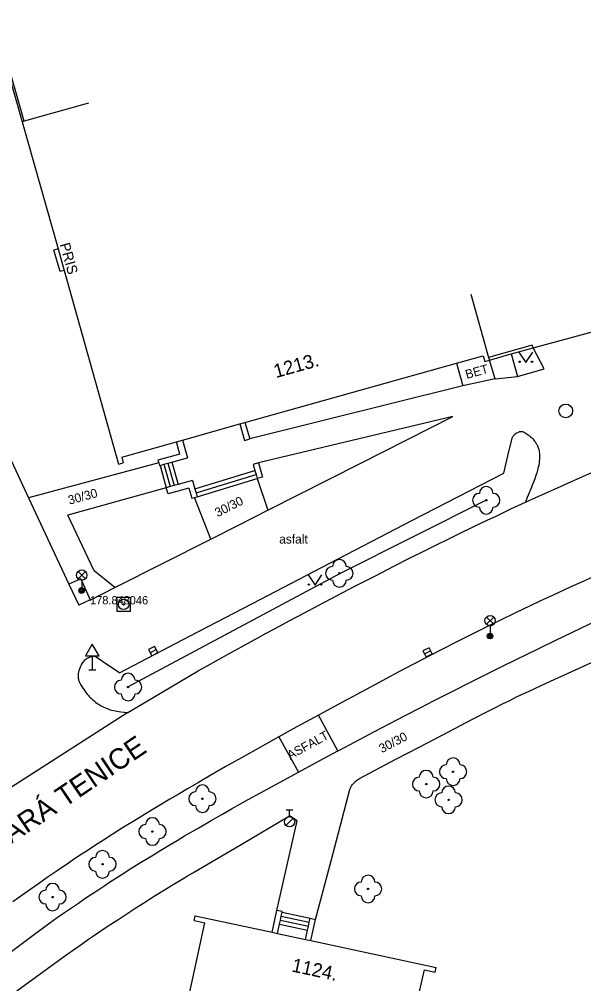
# Model space of a CAD drawing. Extents: x -538441 to -536770, y -1181008 to -1179809.
# Drawn here: x -538238.9 to -538197.8, y -1180684 to -1180613.8 of the extents above; entities that cross this region are included whole.
import ezdxf

# ---------------------------------------------------------------- set-up
doc = ezdxf.new("R2010")
doc.units = 0
for name, color, linetype in [('Vrstva 10', 7, 'Continuous'), ('Vrstva 11', 7, 'Continuous'), ('Vrstva 21', 7, 'Continuous'), ('Vrstva 22', 7, 'Continuous'), ('Vrstva 23', 7, 'Continuous'), ('Vrstva 24', 7, 'Continuous'), ('Vrstva 26', 7, 'Continuous'), ('Vrstva 27', 7, 'Continuous'), ('Vrstva 28', 7, 'Continuous'), ('Vrstva 33', 7, 'Continuous'), ('Vrstva 34', 7, 'Continuous'), ('Vrstva 36', 7, 'Continuous'), ('Vrstva 40', 7, 'Continuous'), ('Vrstva 41', 7, 'Continuous'), ('Vrstva 47', 7, 'Continuous'), ('Vrstva 49', 7, 'Continuous'), ('Vrstva 5', 7, 'Continuous'), ('Vrstva 7', 7, 'Continuous'), ('Vrstva 8', 7, 'Continuous')]:
    doc.layers.add(name, color=color, linetype=linetype)

msp = doc.modelspace()

# ---------------------------------------------------------------- linework, layer by layer
at = {"layer": 'Vrstva 10'}
for p, q in [((-538199.896, -1180648.017), (-538198.65, -1180647.463)), ((-538209.361, -1180652.506), (-538208.449, -1180652.053)), ((-538219.161, -1180657.587), (-538218.102, -1180657.023)), ((-538202.747, -1180657.031), (-538203.82, -1180657.55)), ((-538230.97, -1180664.27), (-538240.97, -1180670.69)), ((-538219.959, -1180666.056), (-538221.314, -1180666.809))]:
    msp.add_line(p, q, dxfattribs=at)
for points in [[(-538198.65, -1180647.463), (-538197.557, -1180646.984), (-538196.599, -1180646.568), (-538195.76, -1180646.207), (-538194.289, -1180645.581), (-538193.184, -1180645.116), (-538191.524, -1180644.425), (-538189.86, -1180643.74)], [(-538208.449, -1180652.053), (-538207.651, -1180651.659), (-538206.951, -1180651.317), (-538205.724, -1180650.722), (-538204.801, -1180650.281), (-538204.108, -1180649.952), (-538203.065, -1180649.464), (-538202.02, -1180648.98), (-538201.267, -1180648.636), (-538200.56, -1180648.315), (-538199.896, -1180648.017)], [(-538218.102, -1180657.023), (-538217.108, -1180656.497), (-538216.176, -1180656.006), (-538215.301, -1180655.547), (-538214.48, -1180655.119), (-538212.938, -1180654.321), (-538211.585, -1180653.629), (-538210.4, -1180653.028), (-538209.361, -1180652.506)], [(-538193.819, -1180652.953), (-538195.079, -1180653.506), (-538196.179, -1180653.994), (-538197.14, -1180654.425), (-538197.98, -1180654.805), (-538198.713, -1180655.14), (-538199.995, -1180655.731), (-538200.954, -1180656.18), (-538201.672, -1180656.518), (-538202.747, -1180657.031)], [(-538230.97, -1180664.27), (-538226.615, -1180661.704), (-538225.831, -1180661.254), (-538225.143, -1180660.863), (-538224.54, -1180660.523), (-538223.483, -1180659.932), (-538222.687, -1180659.492), (-538221.491, -1180658.838), (-538220.891, -1180658.513), (-538220.29, -1180658.19), (-538219.161, -1180657.587)], [(-538203.82, -1180657.55), (-538204.473, -1180657.869), (-538205.612, -1180658.431), (-538206.465, -1180658.858), (-538207.103, -1180659.18), (-538208.058, -1180659.667), (-538209.01, -1180660.16), (-538210.023, -1180660.69), (-538210.907, -1180661.156), (-538212.452, -1180661.976)], [(-538212.452, -1180661.976), (-538213.608, -1180662.596), (-538215.34, -1180663.53), (-538217.07, -1180664.47), (-538218.023, -1180664.99), (-538218.915, -1180665.48), (-538219.751, -1180665.94), (-538219.959, -1180666.056)], [(-538221.314, -1180666.809), (-538222.679, -1180667.575), (-538223.87, -1180668.25), (-538224.909, -1180668.846), (-538225.816, -1180669.371), (-538226.609, -1180669.834), (-538227.3, -1180670.241), (-538227.904, -1180670.6), (-538228.959, -1180671.232), (-538229.747, -1180671.711)], [(-538229.747, -1180671.711), (-538230.337, -1180672.072), (-538231.22, -1180672.618)], [(-538231.22, -1180672.618), (-538232.1, -1180673.17), (-538232.725, -1180673.567), (-538233.308, -1180673.942), (-538233.854, -1180674.297), (-538234.363, -1180674.632), (-538234.839, -1180674.948), (-538235.284, -1180675.246), (-538236.115, -1180675.81), (-538236.839, -1180676.307), (-538237.47, -1180676.746), (-538238.02, -1180677.133), (-538238.5, -1180677.474), (-538239.337, -1180678.074)]]:
    msp.add_lwpolyline(points, dxfattribs=at)
at = {"layer": 'Vrstva 11'}
for p, q in [((-538200.65, -1180639.26), (-538201.46, -1180637.72)), ((-538204.21, -1180639.98), (-538204.64, -1180638.63)), ((-538203.051, -1180638.175), (-538202.58, -1180639.82)), ((-538207.031, -1180638.847), (-538206.57, -1180640.49)), ((-538202.58, -1180639.82), (-538200.65, -1180639.26)), ((-538204.21, -1180639.98), (-538206.57, -1180640.49)), ((-538204.21, -1180639.98), (-538202.58, -1180639.82)), ((-538206.57, -1180640.49), (-538222.08, -1180644.36)), ((-538207.3, -1180642.74), (-538221.44, -1180646.11)), ((-538214.04, -1180646.15), (-538207.3, -1180642.74)), ((-538228.715, -1180646.116), (-538238.189, -1180648.646)), ((-538228.618, -1180646.287), (-538228.16, -1180647.92)), ((-538228.329, -1180646.206), (-538227.871, -1180647.838)), ((-538228.04, -1180646.125), (-538227.582, -1180647.758)), ((-538227.751, -1180646.044), (-538227.293, -1180647.677)), ((-538220.78, -1180649.56), (-538214.04, -1180646.15)), ((-538226.076, -1180647.993), (-538221.707, -1180646.669)), ((-538225.995, -1180648.282), (-538221.626, -1180646.958)), ((-538210.225, -1180650.286), (-538203.59, -1180646.85)), ((-538225.914, -1180648.572), (-538221.545, -1180647.248)), ((-538221.545, -1180647.248), (-538220.78, -1180649.56)), ((-538228.16, -1180647.92), (-538235.33, -1180649.91)), ((-538224.92, -1180651.66), (-538226.106, -1180648.626)), ((-538233.41, -1180653.97), (-538235.33, -1180649.91)), ((-538216.86, -1180653.723), (-538210.225, -1180650.286)), ((-538231.897, -1180655.183), (-538233.41, -1180653.97)), ((-538221.28, -1180656.02), (-538216.86, -1180653.723)), ((-538234.39, -1180654.54), (-538235.255, -1180654.938)), ((-538233.71, -1180656.07), (-538234.54, -1180656.47)), ((-538197.992, -1180658.15), (-538196.13, -1180657.26)), ((-538231.57, -1180661.4), (-538226.426, -1180658.708)), ((-538207.341, -1180662.749), (-538205.97, -1180662.06)), ((-538215.677, -1180667.085), (-538217.07, -1180664.47)), ((-538219.959, -1180666.056), (-538218.54, -1180668.62)), ((-538220.111, -1180678.686), (-538218.64, -1180672.17)), ((-538218.64, -1180672.17), (-538219.18, -1180671.81)), ((-538219.856, -1180679.408), (-538217.815, -1180679.846)), ((-538219.793, -1180679.115), (-538217.752, -1180679.553)), ((-538219.731, -1180678.822), (-538217.69, -1180679.26)), ((-538219.919, -1180679.701), (-538217.878, -1180680.139))]:
    msp.add_line(p, q, dxfattribs=at)
for points in [[(-538242.39, -1180639.64), (-538238.189, -1180648.646)], [(-538203.59, -1180646.85), (-538203.285, -1180645.585), (-538202.98, -1180644.32), (-538202.972, -1180644.292), (-538202.951, -1180644.239), (-538202.924, -1180644.19), (-538202.894, -1180644.145), (-538202.861, -1180644.104), (-538202.828, -1180644.068), (-538202.794, -1180644.034), (-538202.76, -1180644.005), (-538202.692, -1180643.954), (-538202.63, -1180643.914), (-538202.574, -1180643.884), (-538202.525, -1180643.861), (-538202.482, -1180643.845), (-538202.444, -1180643.833), (-538202.412, -1180643.825), (-538202.357, -1180643.815), (-538202.317, -1180643.813), (-538202.288, -1180643.813), (-538202.248, -1180643.819), (-538202.21, -1180643.83), (-538202.167, -1180643.848), (-538202.125, -1180643.867), (-538202.042, -1180643.91), (-538201.962, -1180643.957), (-538201.887, -1180644.006), (-538201.817, -1180644.056), (-538201.751, -1180644.107), (-538201.69, -1180644.158), (-538201.634, -1180644.208), (-538201.582, -1180644.257), (-538201.487, -1180644.353), (-538201.408, -1180644.442), (-538201.344, -1180644.523), (-538201.29, -1180644.596), (-538201.247, -1180644.661), (-538201.211, -1180644.719), (-538201.181, -1180644.77), (-538201.135, -1180644.861), (-538201.105, -1180644.93), (-538201.085, -1180644.983), (-538201.06, -1180645.061), (-538201.04, -1180645.14), (-538201.022, -1180645.238), (-538201.008, -1180645.333), (-538200.998, -1180645.425), (-538200.992, -1180645.515), (-538200.988, -1180645.602), (-538200.988, -1180645.686), (-538200.99, -1180645.768), (-538200.994, -1180645.848), (-538201.007, -1180646.003), (-538201.026, -1180646.148), (-538201.049, -1180646.284), (-538201.075, -1180646.412), (-538201.103, -1180646.532), (-538201.131, -1180646.644), (-538201.192, -1180646.854), (-538201.251, -1180647.037), (-538201.306, -1180647.197), (-538201.409, -1180647.474), (-538201.49, -1180647.681), (-538201.614, -1180647.986), (-538201.737, -1180648.285), (-538201.878, -1180648.632), (-538202.02, -1180648.98)], [(-538238.189, -1180648.646), (-538235.255, -1180654.938)], [(-538224.92, -1180651.66), (-538222.85, -1180650.61), (-538220.78, -1180649.56)], [(-538233.7, -1180656.093), (-538231.897, -1180655.183), (-538224.92, -1180651.66)], [(-538234.39, -1180654.54), (-538233.71, -1180656.07), (-538233.7, -1180656.093)], [(-538235.255, -1180654.938), (-538234.54, -1180656.47)], [(-538226.426, -1180658.708), (-538223.854, -1180657.362), (-538221.28, -1180656.02)], [(-538205.97, -1180662.06), (-538204.745, -1180661.449), (-538203.672, -1180660.917), (-538202.732, -1180660.454), (-538201.086, -1180659.648), (-538199.85, -1180659.046), (-538197.992, -1180658.15)], [(-538231.57, -1180661.4), (-538232.415, -1180660.825), (-538233.26, -1180660.25), (-538233.3, -1180660.227), (-538233.34, -1180660.21), (-538233.378, -1180660.2), (-538233.415, -1180660.193), (-538233.451, -1180660.191), (-538233.485, -1180660.191), (-538233.517, -1180660.193), (-538233.579, -1180660.203), (-538233.633, -1180660.217), (-538233.681, -1180660.232), (-538233.765, -1180660.266), (-538233.827, -1180660.296), (-538233.917, -1180660.346), (-538234.003, -1180660.401), (-538234.057, -1180660.44), (-538234.1, -1180660.475), (-538234.134, -1180660.507), (-538234.19, -1180660.567), (-538234.228, -1180660.614), (-538234.281, -1180660.689), (-538234.33, -1180660.77), (-538234.371, -1180660.847), (-538234.408, -1180660.921), (-538234.439, -1180660.992), (-538234.467, -1180661.06), (-538234.49, -1180661.125), (-538234.51, -1180661.186), (-538234.527, -1180661.244), (-538234.553, -1180661.354), (-538234.569, -1180661.45), (-538234.579, -1180661.534), (-538234.582, -1180661.608), (-538234.582, -1180661.671), (-538234.579, -1180661.726), (-538234.575, -1180661.774), (-538234.562, -1180661.856), (-538234.547, -1180661.917), (-538234.534, -1180661.961), (-538234.51, -1180662.027), (-538234.48, -1180662.09), (-538234.397, -1180662.243), (-538234.314, -1180662.385), (-538234.231, -1180662.516), (-538234.149, -1180662.636), (-538234.069, -1180662.747), (-538233.99, -1180662.849), (-538233.914, -1180662.943), (-538233.841, -1180663.028), (-538233.769, -1180663.107), (-538233.701, -1180663.179), (-538233.635, -1180663.245), (-538233.507, -1180663.364), (-538233.392, -1180663.464), (-538233.287, -1180663.546), (-538233.193, -1180663.616), (-538233.109, -1180663.673), (-538233.034, -1180663.722), (-538232.899, -1180663.802), (-538232.796, -1180663.857), (-538232.717, -1180663.896), (-538232.596, -1180663.951), (-538232.472, -1180664), (-538232.348, -1180664.044), (-538232.239, -1180664.078), (-538232.144, -1180664.105), (-538231.977, -1180664.147), (-538231.852, -1180664.172), (-538231.757, -1180664.189), (-538231.615, -1180664.21), (-538231.471, -1180664.225), (-538231.22, -1180664.248), (-538230.97, -1180664.27)], [(-538200.181, -1180661.996), (-538198.9, -1180661.417), (-538196.977, -1180660.553)], [(-538208.039, -1180665.911), (-538205.869, -1180664.777), (-538204.782, -1180664.214), (-538204.237, -1180663.935), (-538203.69, -1180663.66), (-538203.157, -1180663.397), (-538202.657, -1180663.153), (-538202.186, -1180662.928), (-538201.743, -1180662.719), (-538200.911, -1180662.331), (-538200.181, -1180661.996)], [(-538215.61, -1180667.049), (-538214.411, -1180666.413), (-538213.361, -1180665.858), (-538212.441, -1180665.376), (-538210.829, -1180664.536), (-538209.618, -1180663.911), (-538208.708, -1180663.444), (-538207.341, -1180662.749)], [(-538214.724, -1180669.723), (-538214.698, -1180669.673), (-538214.672, -1180669.627), (-538214.617, -1180669.544), (-538214.563, -1180669.475), (-538214.513, -1180669.417), (-538214.466, -1180669.368), (-538214.423, -1180669.327), (-538214.344, -1180669.259), (-538214.283, -1180669.212), (-538214.236, -1180669.178), (-538214.164, -1180669.132), (-538214.09, -1180669.09), (-538212.58, -1180668.287), (-538211.446, -1180667.689), (-538209.744, -1180666.798), (-538208.039, -1180665.911)], [(-538216.978, -1180667.78), (-538215.677, -1180667.085), (-538215.61, -1180667.049)], [(-538224.901, -1180672.149), (-538224.111, -1180671.698), (-538223.419, -1180671.306), (-538222.204, -1180670.625), (-538221.291, -1180670.119), (-538219.917, -1180669.367), (-538218.54, -1180668.62), (-538216.978, -1180667.78)], [(-538217.298, -1180679.343), (-538216.044, -1180674.622), (-538214.79, -1180669.9), (-538214.771, -1180669.836), (-538214.748, -1180669.777), (-538214.724, -1180669.723)], [(-538233.157, -1180677.211), (-538232.715, -1180676.92), (-538232.285, -1180676.639), (-538231.449, -1180676.101), (-538230.661, -1180675.602), (-538229.92, -1180675.139), (-538229.222, -1180674.709), (-538228.566, -1180674.309), (-538227.95, -1180673.937), (-538227.37, -1180673.591), (-538226.825, -1180673.268), (-538225.801, -1180672.668), (-538224.901, -1180672.149)], [(-538227.776, -1180676.877), (-538227.008, -1180676.412), (-538226.622, -1180676.181), (-538226.235, -1180675.953), (-538222.708, -1180673.882), (-538219.18, -1180671.81)], [(-538234.082, -1180677.828), (-538233.613, -1180677.514), (-538233.157, -1180677.211)], [(-538230.962, -1180678.888), (-538230.378, -1180678.511), (-538229.865, -1180678.183), (-538228.965, -1180677.614), (-538228.287, -1180677.191), (-538227.776, -1180676.877)], [(-538241.881, -1180683.544), (-538240.859, -1180682.754), (-538240.089, -1180682.165), (-538239.51, -1180681.726), (-538238.637, -1180681.071), (-538237.76, -1180680.42), (-538237.19, -1180680.003), (-538236.635, -1180679.603), (-538236.096, -1180679.219), (-538235.571, -1180678.85), (-538235.06, -1180678.496), (-538234.564, -1180678.155), (-538234.082, -1180677.828)], [(-538239.053, -1180684.554), (-538235.747, -1180682.149), (-538234.917, -1180681.555), (-538234.291, -1180681.113), (-538233.819, -1180680.785), (-538233.464, -1180680.541), (-538232.929, -1180680.178), (-538232.39, -1180679.82), (-538231.629, -1180679.322), (-538230.962, -1180678.888)]]:
    msp.add_lwpolyline(points, dxfattribs=at)
at = {"layer": 'Vrstva 21'}
for p, q in [((-538204.87, -1180648.83), (-538215.51, -1180654.15)), ((-538215.51, -1180654.15), (-538230.99, -1180662.43))]:
    msp.add_line(p, q, dxfattribs=at)
for radius in [0.375, 0.05]:
    msp.add_circle((-538231.27, -1180656.41), radius, dxfattribs=at)
at = {"layer": 'Vrstva 22'}
for centre in [(-538204.87, -1180648.83), (-538215.56, -1180654.15), (-538230.94, -1180662.43), (-538207.278, -1180668.593), (-538209.24, -1180669.494), (-538225.53, -1180670.56), (-538207.609, -1180670.64), (-538229.168, -1180672.948), (-538232.805, -1180675.335), (-538213.47, -1180677.13), (-538236.442, -1180677.722)]:
    msp.add_circle(centre, 0.05, dxfattribs=at)
for centre, start, end in [((-538204.87, -1180648.33), 0, 180), ((-538205.37, -1180648.83), 90, 270), ((-538204.37, -1180648.83), 270, 90), ((-538204.87, -1180649.33), 180, 0), ((-538215.56, -1180653.65), 0, 180), ((-538216.06, -1180654.15), 90, 270), ((-538215.06, -1180654.15), 270, 90), ((-538215.56, -1180654.65), 180, 0), ((-538230.94, -1180661.93), 0, 180), ((-538231.44, -1180662.43), 90, 270), ((-538230.44, -1180662.43), 270, 90), ((-538230.94, -1180662.93), 180, 0), ((-538207.778, -1180668.593), 90, 270), ((-538207.278, -1180668.093), 0, 180), ((-538206.778, -1180668.593), 270, 90), ((-538209.24, -1180668.994), 0, 180), ((-538225.53, -1180670.06), 0, 180), ((-538209.74, -1180669.494), 90, 270), ((-538208.74, -1180669.494), 270, 90), ((-538207.278, -1180669.093), 180, 0), ((-538226.03, -1180670.56), 90, 270), ((-538225.03, -1180670.56), 270, 90), ((-538209.24, -1180669.994), 180, 0), ((-538208.109, -1180670.64), 90, 270), ((-538207.609, -1180670.14), 0, 180), ((-538207.109, -1180670.64), 270, 90), ((-538225.53, -1180671.06), 180, 0), ((-538207.609, -1180671.14), 180, 0), ((-538229.168, -1180672.448), 0, 180), ((-538229.668, -1180672.948), 90, 270), ((-538228.668, -1180672.948), 270, 90), ((-538229.168, -1180673.448), 180, 0), ((-538232.805, -1180674.835), 0, 180), ((-538233.305, -1180675.335), 90, 270), ((-538232.305, -1180675.335), 270, 90), ((-538232.805, -1180675.835), 180, 0), ((-538213.97, -1180677.13), 90, 270), ((-538213.47, -1180676.63), 0, 180), ((-538212.97, -1180677.13), 270, 90), ((-538236.942, -1180677.722), 90, 270), ((-538236.442, -1180677.222), 0, 180), ((-538235.942, -1180677.722), 270, 90), ((-538213.47, -1180677.63), 180, 0), ((-538236.442, -1180678.222), 180, 0)]:
    msp.add_arc(centre, 0.5, start, end, dxfattribs=at)
at = {"layer": 'Vrstva 24'}
for p, q in [((-538236.046, -1180630.524), (-538236.35, -1180630.61)), ((-538235.89, -1180632.17), (-538236.35, -1180630.61)), ((-538235.605, -1180632.09), (-538235.89, -1180632.17))]:
    msp.add_line(p, q, dxfattribs=at)
at = {"layer": 'Vrstva 26'}
msp.add_lwpolyline([(-538231.77, -1180656.91), (-538230.77, -1180656.91), (-538230.77, -1180655.91), (-538231.77, -1180655.91)], close=True, dxfattribs=at)
at = {"layer": 'Vrstva 27'}
for p, q in [((-538229.342, -1180659.926), (-538228.898, -1180659.694)), ((-538209.36, -1180660.016), (-538208.916, -1180659.784))]:
    msp.add_line(p, q, dxfattribs=at)
for points in [[(-538229.226, -1180660.147), (-538228.783, -1180659.916), (-538229.014, -1180659.473), (-538229.457, -1180659.704)], [(-538209.244, -1180660.237), (-538208.801, -1180660.006), (-538209.032, -1180659.563), (-538209.475, -1180659.794)]]:
    msp.add_lwpolyline(points, close=True, dxfattribs=at)
msp.add_circle((-538199.08, -1180642.33), 0.5, dxfattribs=at)
at = {"layer": 'Vrstva 28'}
for p, q in [((-538219.44, -1180671.365), (-538218.94, -1180671.365)), ((-538219.19, -1180671.865), (-538219.19, -1180671.365)), ((-538219.448, -1180672.512), (-538218.918, -1180671.982))]:
    msp.add_line(p, q, dxfattribs=at)
msp.add_circle((-538219.19, -1180672.24), 0.375, dxfattribs=at)
at = {"layer": 'Vrstva 33'}
for p, q in [((-538234.585, -1180654.54), (-538234.055, -1180654.01)), ((-538234.585, -1180654.01), (-538234.055, -1180654.54)), ((-538234.32, -1180654.65), (-538234.32, -1180655.4)), ((-538204.855, -1180657.86), (-538204.325, -1180657.33)), ((-538204.855, -1180657.33), (-538204.325, -1180657.86)), ((-538204.59, -1180657.97), (-538204.59, -1180658.72))]:
    msp.add_line(p, q, dxfattribs=at)
for centre, radius in [((-538234.32, -1180654.275), 0.375), ((-538234.32, -1180655.4), 0.2), ((-538234.32, -1180655.4), 0.145), ((-538234.32, -1180655.4), 0.0876), ((-538204.59, -1180657.595), 0.375), ((-538204.59, -1180658.72), 0.2), ((-538204.59, -1180658.72), 0.145), ((-538204.59, -1180658.72), 0.0876)]:
    msp.add_circle(centre, radius, dxfattribs=at)
at = {"layer": 'Vrstva 34'}
for p, q in [((-538233.55, -1180660.162), (-538233.55, -1180661.18)), ((-538233.8, -1180661.18), (-538233.3, -1180661.18))]:
    msp.add_line(p, q, dxfattribs=at)
msp.add_lwpolyline([(-538234.05, -1180660.162), (-538233.05, -1180660.162), (-538233.55, -1180659.296)], close=True, dxfattribs=at)
at = {"layer": 'Vrstva 36'}
for points in [[(-538202.484, -1180638.043), (-538201.984, -1180638.793), (-538201.484, -1180638.043)], [(-538217.835, -1180654.268), (-538217.335, -1180655.018), (-538216.835, -1180654.268)]]:
    msp.add_lwpolyline(points, dxfattribs=at)
for centre in [(-538202.434, -1180638.743), (-538201.535, -1180638.743), (-538217.785, -1180654.968), (-538216.886, -1180654.968)]:
    msp.add_circle(centre, 0.05, dxfattribs=at)
at = {"layer": 'Vrstva 5'}
for p, q in [((-538233.837, -1180619.924), (-538238.506, -1180621.239)), ((-538238.506, -1180621.239), (-538238.65, -1180621.28)), ((-538238.65, -1180621.28), (-538236.046, -1180630.524)), ((-538236.046, -1180630.524), (-538235.605, -1180632.09)), ((-538235.605, -1180632.09), (-538231.63, -1180646.2)), ((-538205.99, -1180633.816), (-538204.694, -1180638.438)), ((-538207.031, -1180638.847), (-538205.094, -1180638.304)), ((-538205.094, -1180638.304), (-538204.976, -1180638.724)), ((-538204.976, -1180638.724), (-538204.64, -1180638.63)), ((-538204.694, -1180638.438), (-538204.64, -1180638.63)), ((-538222.45, -1180643.17), (-538207.031, -1180638.847)), ((-538226.99, -1180644.446), (-538222.801, -1180643.271)), ((-538222.801, -1180643.271), (-538222.45, -1180643.17)), ((-538231.411, -1180645.686), (-538227.43, -1180644.57)), ((-538227.43, -1180644.57), (-538226.99, -1180644.446)), ((-538231.411, -1180645.686), (-538231.293, -1180646.105)), ((-538231.63, -1180646.2), (-538231.293, -1180646.105)), ((-538226.133, -1180679.422), (-538226.06, -1180679.08)), ((-538226.133, -1180679.422), (-538225.35, -1180679.59)), ((-538226.06, -1180679.08), (-538220.453, -1180680.281)), ((-538229.21, -1180697.32), (-538225.35, -1180679.59)), ((-538220.453, -1180680.281), (-538220.062, -1180680.365)), ((-538220.062, -1180680.365), (-538218.02, -1180680.802)), ((-538218.02, -1180680.802), (-538217.628, -1180680.886)), ((-538217.628, -1180680.886), (-538208.51, -1180682.84)), ((-538208.583, -1180683.182), (-538208.51, -1180682.84)), ((-538213.43, -1180700.24), (-538209.365, -1180683.014)), ((-538209.365, -1180683.014), (-538208.583, -1180683.182))]:
    msp.add_line(p, q, dxfattribs=at)
at = {"layer": 'Vrstva 7'}
for p, q in [((-538240.74, -1180613.99), (-538238.65, -1180621.28)), ((-538238.506, -1180621.239), (-538240.635, -1180613.811)), ((-538201.515, -1180637.528), (-538204.694, -1180638.438)), ((-538222.45, -1180643.17), (-538222.08, -1180644.36)), ((-538227.176, -1180645.473), (-538227.43, -1180644.57)), ((-538226.99, -1180644.446), (-538226.63, -1180645.73)), ((-538220.453, -1180680.281), (-538220.111, -1180678.686)), ((-538217.628, -1180680.886), (-538217.298, -1180679.343))]:
    msp.add_line(p, q, dxfattribs=at)
for points in [[(-538204.64, -1180638.63), (-538203.051, -1180638.175), (-538201.46, -1180637.72), (-538201.515, -1180637.528)], [(-538222.801, -1180643.271), (-538222.465, -1180644.468), (-538222.08, -1180644.36)], [(-538227.176, -1180645.473), (-538228.77, -1180645.92), (-538228.715, -1180646.116), (-538228.663, -1180646.3)], [(-538228.663, -1180646.3), (-538228.618, -1180646.287), (-538228.329, -1180646.206), (-538228.04, -1180646.125), (-538227.751, -1180646.044), (-538226.63, -1180645.73)], [(-538221.44, -1180646.11), (-538221.833, -1180646.22), (-538221.707, -1180646.669), (-538221.626, -1180646.958), (-538221.545, -1180647.248)], [(-538221.44, -1180646.11), (-538221.16, -1180647.14), (-538221.545, -1180647.248)], [(-538226.247, -1180647.384), (-538227.293, -1180647.677), (-538227.582, -1180647.758), (-538227.871, -1180647.838), (-538228.16, -1180647.92)], [(-538226.247, -1180647.384), (-538226.076, -1180647.993), (-538225.995, -1180648.282), (-538225.914, -1180648.572)], [(-538226.51, -1180647.94), (-538228.035, -1180648.367), (-538228.16, -1180647.92)], [(-538226.51, -1180647.94), (-538226.3, -1180648.68), (-538226.106, -1180648.626), (-538225.914, -1180648.572)], [(-538220.062, -1180680.365), (-538219.919, -1180679.701), (-538219.856, -1180679.408), (-538219.793, -1180679.115), (-538219.731, -1180678.822), (-538219.72, -1180678.77), (-538220.111, -1180678.686)], [(-538218.02, -1180680.802), (-538217.878, -1180680.139), (-538217.815, -1180679.846), (-538217.752, -1180679.553), (-538217.69, -1180679.26), (-538217.298, -1180679.343)]]:
    msp.add_lwpolyline(points, dxfattribs=at)
at = {"layer": 'Vrstva 8'}
msp.add_line((-538201.46, -1180637.72), (-538195.21, -1180636.04), dxfattribs=at)

# ---------------------------------------------------------------- texts
at = {"layer": 'Vrstva 22'}
msp.add_text('178.84 ', height=0.6, dxfattribs=at).set_placement((-538233.715, -1180656.41))
at = {"layer": 'Vrstva 23'}
msp.add_text('8046', height=0.6, dxfattribs=at).set_placement((-538231.27, -1180656.41))
at = {"layer": 'Vrstva 40'}
for s, rotation, p in [('BET', 15.66897, (-538206.286, -1180639.998)), ('30/30', 15.20063, (-538235.215, -1180649.154)), ('30/30', 26.93735, (-538224.427, -1180650.069)), ('ASFALT', 28.79276, (-538219.149, -1180667.733)), ('30/30', 27.53903, (-538212.469, -1180667.249))]:
    msp.add_text(s, height=0.65, rotation=rotation, dxfattribs=at).set_placement(p)
msp.add_text('asfalt', height=0.65, dxfattribs=at).set_placement((-538219.941, -1180651.981))
at = {"layer": 'Vrstva 41'}
msp.add_text('PRIS', height=0.75, rotation=285.73261, dxfattribs=at).set_placement((-538235.93, -1180630.198))
at = {"layer": 'Vrstva 47'}
for s, rotation, p in [('1213.', 15.66897, (-538220.185, -1180639.941)), ('1124.', 347.90747, (-538219.087, -1180683.131))]:
    msp.add_text(s, height=1, rotation=rotation, dxfattribs=at).set_placement(p)
at = {"layer": 'Vrstva 49'}
msp.add_text('Ul. STARÁ TENICE ', height=1.5, rotation=34.1145, dxfattribs=at).set_placement((-538244.064, -1180676.993))

doc.saveas('drawing.dxf')
